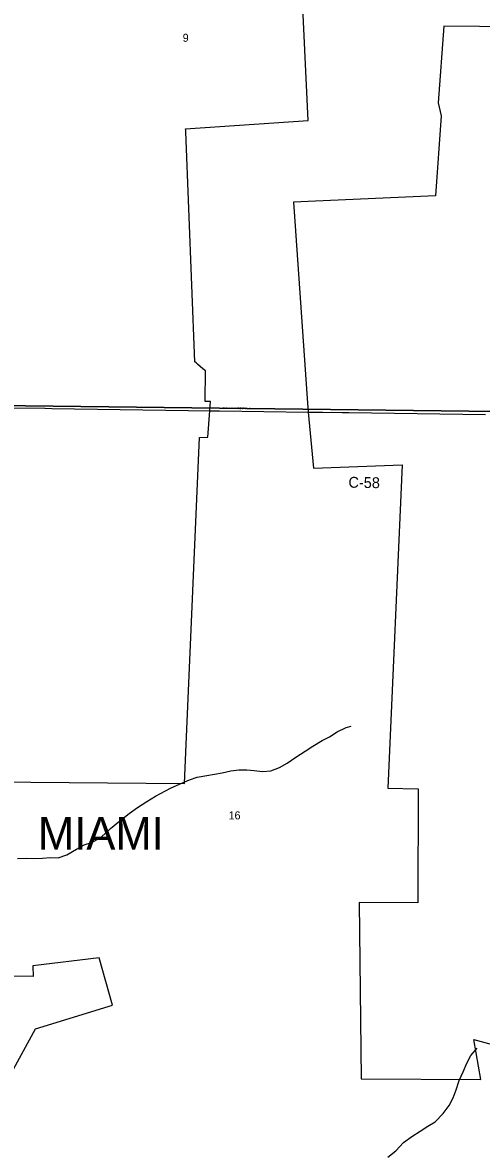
# Model space of a CAD drawing. Extents: x 1312308 to 1684953, y 460642 to 865172.
# Drawn here: x 1455224 to 1458390, y 593265 to 601064 of the extents above; entities that cross this region are included whole.
import ezdxf

# ---------------------------------------------------------------- set-up
doc = ezdxf.new("R2010")
doc.units = 0
for name, color, linetype in [('GM_X_City_Street', 7, 'Continuous'), ('GM_X_City_Street_Text', 7, 'Continuous'), ('GM_X_Corporation', 7, 'Continuous'), ('GM_X_County_Road', 7, 'Continuous'), ('GM_X_County_Road_Text', 7, 'Continuous'), ('GM_X_Minor_River', 7, 'Continuous'), ('GM_X_Section', 7, 'Continuous'), ('GM_X_Section_Text', 7, 'Continuous'), ('GM_X_Township_Text', 7, 'Continuous')]:
    doc.layers.add(name, color=color, linetype=linetype)

msp = doc.modelspace()

# ---------------------------------------------------------------- linework, layer by layer
at = {"layer": 'GM_X_City_Street'}
msp.add_lwpolyline([(1456583.3, 598383.6), (1457195.7, 598375.4), (1457212.8, 598375.2)], dxfattribs=at)
at = {"layer": 'GM_X_Corporation'}
for points in [[(1453685.2, 595833.3), (1456341.1, 595811.2), (1456352.9, 596080.5), (1456445.5, 598200.3), (1456501.4, 598202.5), (1456515.3, 598384.5), (1456520.2, 598447.3), (1456483.1, 598447.9), (1456484.9, 598658.9), (1456466.7, 598674.9), (1456448.4, 598690.8), (1456430.2, 598706.8), (1456421.1, 598714.8), (1456412, 598722.8), (1456349.6, 600310.2), (1456349.2, 600320.9), (1456348.8, 600331.6), (1457194.9, 600387), (1457115.3, 602045.1)], [(1459115.5, 601030.5), (1458131, 601038.4), (1458130.7, 601038.4), (1458091.7, 600509.8), (1458113.5, 600419.4), (1458072.8, 599866.9), (1457194.1, 599829.4), (1457093, 599825), (1457190, 598437), (1457195.7, 598375.4), (1457231.1, 597987.9), (1457844.6, 598012), (1457743.9, 595780.2), (1457743.9, 595779.3), (1457953.7, 595775.6), (1457951.4, 594988.6), (1457547.4, 594990.5), (1457560.4, 593771.6), (1458387.4, 593767.6), (1458338.1, 594044.3), (1458979.5, 593868.9)], [(1455019.9, 593585.6), (1455312.9, 594117.2), (1455843, 594281.7), (1455751, 594607.9), (1455293.2, 594553.5), (1455296.7, 594478.6), (1453917.8, 594484)]]:
    msp.add_lwpolyline(points, dxfattribs=at)
at = {"layer": 'GM_X_County_Road'}
for points in [[(1453698.1, 598415.1), (1454508.7, 598409), (1455376.8, 598401.4)], [(1455376.8, 598401.4), (1455378.5, 598401.4), (1455425.9, 598401), (1456369.1, 598386.4), (1456515.3, 598384.5), (1456583.3, 598383.6)], [(1457212.8, 598375.2), (1457296.3, 598374.1), (1457430.1, 598372.3), (1457474.7, 598371.8), (1457475.1, 598371.8)], [(1457475.1, 598371.8), (1458419.3, 598359.3)]]:
    msp.add_lwpolyline(points, dxfattribs=at)
at = {"layer": 'GM_X_Minor_River'}
for points in [[(1456996.3, 595920.8), (1457049, 595952), (1457110, 595993), (1457175, 596033.9), (1457225.8, 596069), (1457290.7, 596108), (1457341.3, 596133.1), (1457394.1, 596168.2), (1457456.8, 596197.2), (1457491.1, 596206.6)], [(1455187.3, 595294.1), (1455247.6, 595297), (1455301.6, 595294), (1455361.9, 595296.9), (1455414.1, 595300), (1455468.2, 595299), (1455528.8, 595320), (1455595.7, 595358.8), (1455648.4, 595388), (1455706.9, 595406.9), (1455765.8, 595442), (1455831.1, 595500.9), (1455894.2, 595553.9), (1455959.4, 595604.9), (1456016.3, 595645.9), (1456081.3, 595686.9), (1456140.2, 595723.9), (1456245.5, 595778.1), (1456310.2, 595809), (1456374.9, 595835.9), (1456429.5, 595855), (1456495.9, 595865.8), (1456548.2, 595874.9), (1456600.5, 595886), (1456660.9, 595898.9), (1456715.2, 595905.9), (1456771.4, 595904.9), (1456821.4, 595900), (1456879.5, 595894.9), (1456937.7, 595897.8), (1456996.3, 595920.8)], [(1457745.4, 593232.2), (1457800.4, 593275.3), (1457853.6, 593332.5), (1457910.6, 593373.6), (1457967.4, 593410.6), (1458020.2, 593445.8), (1458071, 593476.9), (1458126.2, 593534.1), (1458167.4, 593589.4), (1458194.4, 593641.1), (1458215.6, 593696.8), (1458236.8, 593760.6), (1458264, 593820.3), (1458289.2, 593880), (1458318.3, 593933.6), (1458361.4, 593984.9)]]:
    msp.add_lwpolyline(points, dxfattribs=at)
at = {"layer": 'GM_X_Section'}
for points in [[(1453764.9, 603826.9), (1459107.6, 603789.7), (1459068.9, 598373), (1453710.7, 598436.4)], [(1453710.7, 598436.4), (1459068.9, 598373), (1459001, 593019.2), (1453648.4, 593064.9)]]:
    msp.add_lwpolyline(points, close=True, dxfattribs=at)

# ---------------------------------------------------------------- texts
at = {"layer": 'GM_X_City_Street_Text'}
msp.add_text('LOWER MIAMISBURG RD', height=12.5, rotation=358.95823, dxfattribs=at).set_placement((1456592.8, 598397.5))
at = {"layer": 'GM_X_County_Road_Text'}
msp.add_text('C-58', height=75, rotation=358.9701, dxfattribs=at).set_placement((1457471.9, 597853.7))
at = {"layer": 'GM_X_Section_Text'}
for s, height, p in [('9', 55.3, (1456328.5, 600931.6)), ('16', 55.25, (1456645.3, 595563.6))]:
    msp.add_text(s, height=height, rotation=0.00001, dxfattribs=at).set_placement(p)
at = {"layer": 'GM_X_Township_Text'}
msp.add_text('MIAMI', height=225, rotation=0.00001, dxfattribs=at).set_placement((1455329.1, 595354.6))

doc.saveas('drawing.dxf')
